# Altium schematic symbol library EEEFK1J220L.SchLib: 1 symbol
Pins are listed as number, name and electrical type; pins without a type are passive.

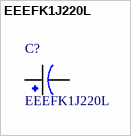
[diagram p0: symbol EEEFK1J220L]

## EEEFK1J220L
designator C?
CAP ALUM 22UF 20% 63V SMD; MF: Panasonic
footprint *CAP_EEEFK1J220L
pins: 1, 2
